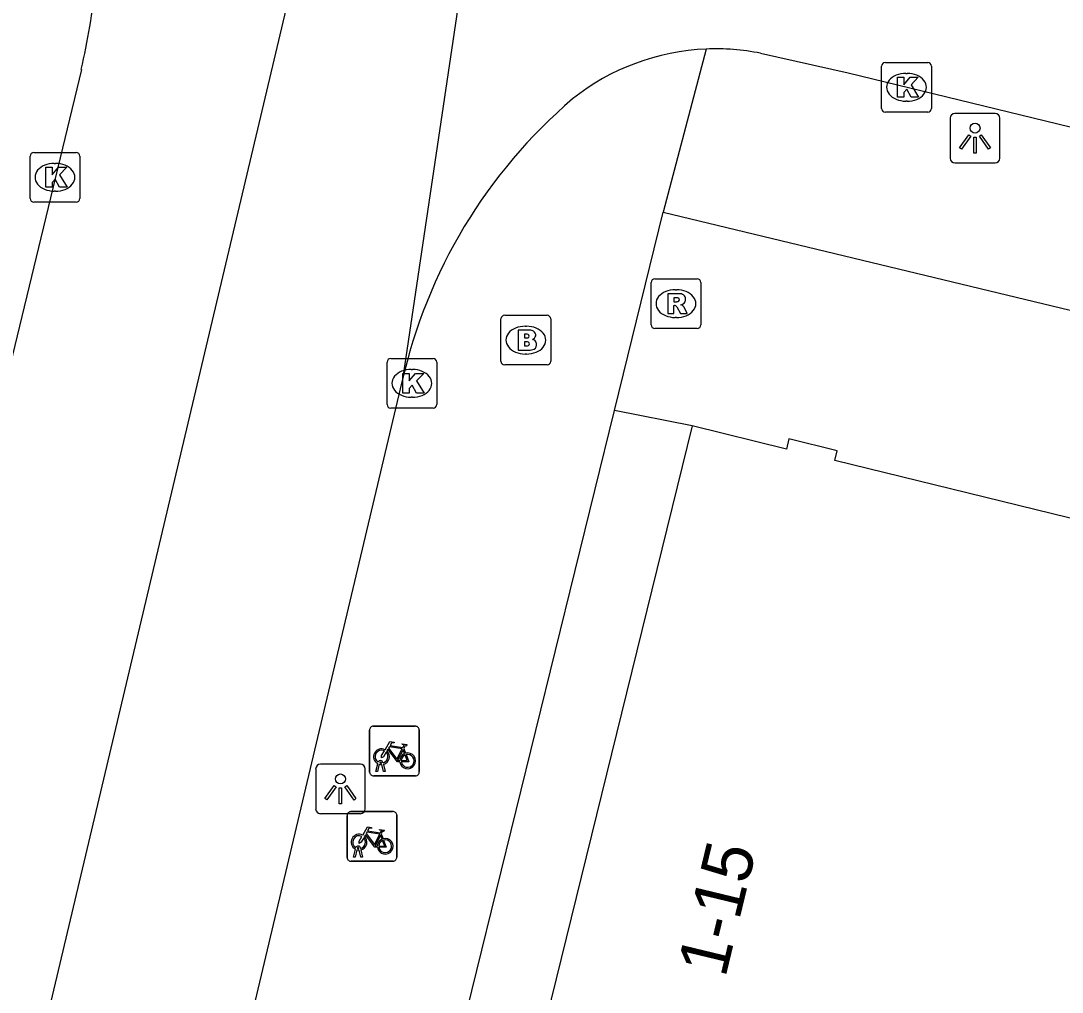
# Model space of a CAD drawing. Extents: x 162812 to 163818, y 381639 to 382470.
# Drawn here: x 163027.55 to 163048.51, y 382341.9 to 382361.46 of the extents above; entities that cross this region are included whole.
import ezdxf

# ---------------------------------------------------------------- set-up
doc = ezdxf.new("R2010")
doc.units = 0
for name, color, linetype in [('IMGEO_Brandkraan', 7, 'Continuous'), ('IMGEO_Fietsenrek', 7, 'Continuous'), ('IMGEO_Kolk', 7, 'Continuous'), ('IMGEO_Lichtpunt', 7, 'Continuous'), ('IMGEO_Pand', 7, 'Continuous'), ('IMGEO_Pand_nummerreeks', 7, 'Continuous'), ('IMGEO_Rijbaan_lokaal_gesloten', 7, 'Continuous'), ('IMGEO_Rijbaan_lokaal_open', 7, 'Continuous'), ('IMGEO_Rioolput', 7, 'Continuous'), ('IMGEO_Voetpad_open', 7, 'Continuous')]:
    doc.layers.add(name, color=color, linetype=linetype)

msp = doc.modelspace()

# ---------------------------------------------------------------- linework, layer by layer
at = {"layer": 'IMGEO_Brandkraan'}
for p, q in [((163037.286, 382355.533), (163038.138, 382355.533)), ((163037.211, 382354.607), (163037.211, 382355.459)), ((163037.699, 382355.313), (163037.724, 382355.313)), ((163038.212, 382355.459), (163038.212, 382354.607)), ((163037.722, 382354.753), (163037.697, 382354.753)), ((163038.138, 382354.533), (163037.286, 382354.533))]:
    msp.add_line(p, q, dxfattribs=at)
for points in [[(163037.286, 382355.533), (163038.138, 382355.533)], [(163037.211, 382354.607), (163037.211, 382355.459)], [(163038.212, 382355.459), (163038.212, 382354.607)], [(163037.559, 382355.233), (163037.559, 382354.833), (163037.772, 382354.833)], [(163037.79, 382355.233), (163037.559, 382355.233)], [(163037.738, 382355.152), (163037.684, 382355.152), (163037.684, 382355.076)], [(163037.684, 382355.076), (163037.737, 382355.076)], [(163037.746, 382355), (163037.684, 382355), (163037.684, 382354.919)], [(163037.684, 382354.919), (163037.746, 382354.919)], [(163038.138, 382354.533), (163037.286, 382354.533)]]:
    msp.add_lwpolyline(points, dxfattribs=at)
for centre, radius, start, end in [((163037.288, 382355.457), 0.0765, 91.552, 178.448), ((163037.288, 382355.457), 0.0765, 91.552, 178.448), ((163038.136, 382355.457), 0.0765, 1.552, 88.448), ((163038.136, 382355.457), 0.0765, 1.552, 88.448), ((163037.739, 382355.114), 0.0379, 267.8285, 90.9355), ((163037.794, 382355.088), 0.145, 59.4692, 91.5367), ((163037.819, 382355.135), 0.0922, 285.5137, 58.1501), ((163037.747, 382354.959), 0.0404, 269.8759, 90.5077), ((163037.778, 382355.084), 0.251, 268.6676, 293.5347), ((163037.824, 382354.943), 0.105, 301.3115, 78.989), ((163037.288, 382354.609), 0.0765, 181.552, 268.448), ((163037.288, 382354.609), 0.0765, 181.552, 268.448), ((163038.136, 382354.609), 0.0765, 271.552, 358.448), ((163038.136, 382354.609), 0.0765, 271.552, 358.448)]:
    msp.add_arc(centre, radius, start, end, dxfattribs=at)
for centre, major_axis, ratio, start_param, end_param in [((163037.698, 382355.033), (-0.387, 0.002), 0.722429, 4.712389, 7.853982), ((163037.723, 382355.033), (-0.39, 0.002), 0.717154, 1.570796, 4.712389)]:
    msp.add_ellipse(centre, major_axis=major_axis, ratio=ratio, start_param=start_param, end_param=end_param, dxfattribs=at)
at = {"layer": 'IMGEO_Fietsenrek'}
for p, q in [((163034.566, 382346.336), (163034.566, 382347.177)), ((163034.566, 382347.177), (163034.566, 382346.336)), ((163034.641, 382347.261), (163035.482, 382347.261)), ((163035.482, 382347.261), (163034.641, 382347.261)), ((163035.566, 382347.186), (163035.566, 382346.345)), ((163035.566, 382346.345), (163035.566, 382347.186)), ((163035.253, 382346.81), (163035.289, 382346.715)), ((163034.693, 382346.345), (163034.732, 382346.505)), ((163034.762, 382346.493), (163034.727, 382346.345)), ((163034.804, 382346.517), (163034.803, 382346.521)), ((163034.845, 382346.345), (163034.811, 382346.487)), ((163034.835, 382346.528), (163034.836, 382346.521)), ((163034.843, 382346.491), (163034.878, 382346.345)), ((163035.491, 382346.261), (163034.65, 382346.261)), ((163034.65, 382346.261), (163035.491, 382346.261)), ((163034.727, 382346.345), (163034.693, 382346.345)), ((163034.878, 382346.345), (163034.845, 382346.345)), ((163034.114, 382344.616), (163034.114, 382345.457)), ((163034.114, 382345.457), (163034.114, 382344.616)), ((163034.189, 382345.541), (163035.03, 382345.541)), ((163035.03, 382345.541), (163034.189, 382345.541)), ((163035.114, 382345.466), (163035.114, 382344.625)), ((163035.114, 382344.625), (163035.114, 382345.466)), ((163034.801, 382345.09), (163034.837, 382344.995)), ((163034.352, 382344.797), (163034.351, 382344.801)), ((163034.383, 382344.808), (163034.384, 382344.801)), ((163034.241, 382344.625), (163034.28, 382344.785)), ((163034.275, 382344.625), (163034.241, 382344.625)), ((163034.31, 382344.773), (163034.275, 382344.625)), ((163034.393, 382344.625), (163034.359, 382344.767)), ((163034.391, 382344.771), (163034.426, 382344.625)), ((163034.426, 382344.625), (163034.393, 382344.625)), ((163035.039, 382344.541), (163034.198, 382344.541)), ((163034.198, 382344.541), (163035.039, 382344.541))]:
    msp.add_line(p, q, dxfattribs=at)
for points in [[(163034.879, 382346.787), (163034.974, 382346.951), (163035.06, 382346.937), (163035.062, 382346.928), (163035.006, 382346.917), (163034.979, 382346.872), (163035.235, 382346.831)], [(163035.235, 382346.831), (163035.26, 382346.88), (163035.254, 382346.884), (163035.231, 382346.888), (163035.219, 382346.895), (163035.218, 382346.898), (163035.22, 382346.903), (163035.315, 382346.888), (163035.317, 382346.878), (163035.307, 382346.865), (163035.295, 382346.859), (163035.281, 382346.865), (163035.253, 382346.81)], [(163034.9, 382346.735), (163034.848, 382346.645), (163034.808, 382346.62), (163034.809, 382346.667), (163034.864, 382346.761)], [(163035.175, 382346.543), (163035.125, 382346.543), (163034.934, 382346.794), (163034.915, 382346.762)], [(163035.222, 382346.806), (163034.965, 382346.847), (163034.948, 382346.818), (163035.115, 382346.598), (163035.222, 382346.806)], [(163035.27, 382346.708), (163035.24, 382346.785), (163035.131, 382346.567), (163035.174, 382346.567)], [(163035.204, 382346.567), (163035.324, 382346.566), (163035.28, 382346.68)], [(163035.3, 382346.687), (163035.355, 382346.542), (163035.205, 382346.542)], [(163034.427, 382345.067), (163034.522, 382345.231), (163034.608, 382345.217), (163034.61, 382345.208), (163034.554, 382345.197), (163034.527, 382345.152), (163034.783, 382345.111)], [(163034.448, 382345.015), (163034.396, 382344.925), (163034.356, 382344.9), (163034.357, 382344.947), (163034.412, 382345.041)], [(163034.723, 382344.823), (163034.673, 382344.823), (163034.482, 382345.074), (163034.463, 382345.042)], [(163034.77, 382345.086), (163034.513, 382345.127), (163034.496, 382345.098), (163034.663, 382344.878), (163034.77, 382345.086)], [(163034.818, 382344.988), (163034.788, 382345.065), (163034.679, 382344.847), (163034.722, 382344.847)], [(163034.783, 382345.111), (163034.808, 382345.16), (163034.802, 382345.164), (163034.779, 382345.168), (163034.767, 382345.175), (163034.766, 382345.178), (163034.768, 382345.183), (163034.863, 382345.168), (163034.865, 382345.158), (163034.855, 382345.145), (163034.843, 382345.139), (163034.829, 382345.145), (163034.801, 382345.09)], [(163034.752, 382344.847), (163034.872, 382344.846), (163034.828, 382344.96)], [(163034.848, 382344.967), (163034.903, 382344.822), (163034.753, 382344.822)]]:
    msp.add_lwpolyline(points, dxfattribs=at)
for centre, radius, start, end in [((163034.644, 382347.183), 0.0779, 92.4484, 184.2845), ((163034.644, 382347.183), 0.0779, 92.4484, 184.2845), ((163035.488, 382347.183), 0.0779, 2.4484, 94.2845), ((163035.488, 382347.183), 0.0779, 2.4484, 94.2845), ((163034.806, 382346.646), 0.159, 62.6766, 242.1369), ((163034.806, 382346.646), 0.129, 63.3192, 238.903), ((163034.806, 382346.646), 0.129, 283.6043, 43.4302), ((163034.806, 382346.646), 0.159, 283.5766, 46.6042), ((163035.333, 382346.562), 0.159, 113.3408, 178.3217), ((163035.333, 382346.562), 0.159, 187.0065, 105.7708), ((163035.333, 382346.562), 0.129, 113.923, 177.9556), ((163035.333, 382346.562), 0.129, 188.6715, 104.5883), ((163034.786, 382346.517), 0.0499, 12.8025, 158.6934), ((163034.806, 382346.646), 0.159, 253.9967, 271.7867), ((163034.786, 382346.517), 0.0174, 12.8025, 163.4502), ((163034.806, 382346.646), 0.129, 253.415, 269.0204), ((163034.644, 382346.339), 0.0779, 182.4484, 274.2845), ((163034.644, 382346.339), 0.0779, 182.4484, 274.2845), ((163035.488, 382346.339), 0.0779, 272.4484, 4.2845), ((163035.488, 382346.339), 0.0779, 272.4484, 4.2845), ((163034.192, 382345.463), 0.0779, 92.4484, 184.2845), ((163034.192, 382345.463), 0.0779, 92.4484, 184.2845), ((163035.036, 382345.463), 0.0779, 2.4484, 94.2845), ((163035.036, 382345.463), 0.0779, 2.4484, 94.2845), ((163034.354, 382344.926), 0.159, 62.6766, 242.1369), ((163034.354, 382344.926), 0.129, 63.3192, 238.903), ((163034.354, 382344.926), 0.129, 283.6043, 43.4302), ((163034.354, 382344.926), 0.159, 283.5766, 46.6042), ((163034.881, 382344.842), 0.159, 187.0065, 105.7708), ((163034.334, 382344.797), 0.0499, 12.8025, 158.6934), ((163034.334, 382344.797), 0.0174, 12.8025, 163.4502), ((163034.354, 382344.926), 0.129, 253.415, 269.0204), ((163034.881, 382344.842), 0.159, 113.3408, 178.3217), ((163034.881, 382344.842), 0.129, 113.923, 177.9556), ((163034.881, 382344.842), 0.129, 188.6715, 104.5883), ((163034.192, 382344.619), 0.0779, 182.4484, 274.2845), ((163034.192, 382344.619), 0.0779, 182.4484, 274.2845), ((163034.354, 382344.926), 0.159, 253.9967, 271.7867), ((163035.036, 382344.619), 0.0779, 272.4484, 4.2845), ((163035.036, 382344.619), 0.0779, 272.4484, 4.2845)]:
    msp.add_arc(centre, radius, start, end, dxfattribs=at)
at = {"layer": 'IMGEO_Kolk'}
for p, q in [((163044.874, 382359.698), (163044.874, 382360.55)), ((163044.949, 382360.624), (163045.801, 382360.624)), ((163045.875, 382360.55), (163045.875, 382359.698)), ((163045.362, 382360.404), (163045.387, 382360.404)), ((163045.385, 382359.844), (163045.36, 382359.844)), ((163045.801, 382359.624), (163044.949, 382359.624)), ((163027.731, 382357.886), (163027.731, 382358.738)), ((163027.806, 382358.812), (163028.658, 382358.812)), ((163028.732, 382358.738), (163028.732, 382357.886)), ((163028.219, 382358.592), (163028.244, 382358.592)), ((163028.242, 382358.032), (163028.217, 382358.032)), ((163028.658, 382357.812), (163027.806, 382357.812)), ((163034.992, 382354.663), (163035.844, 382354.663)), ((163034.917, 382353.737), (163034.917, 382354.589)), ((163035.405, 382354.443), (163035.43, 382354.443)), ((163035.918, 382354.589), (163035.918, 382353.737)), ((163035.428, 382353.883), (163035.403, 382353.883)), ((163035.844, 382353.663), (163034.992, 382353.663))]:
    msp.add_line(p, q, dxfattribs=at)
for points in [[(163044.874, 382359.698), (163044.874, 382360.55)], [(163044.949, 382360.624), (163045.801, 382360.624)], [(163045.875, 382360.55), (163045.875, 382359.698)], [(163045.195, 382360.324), (163045.318, 382360.324), (163045.318, 382360.173), (163045.448, 382360.324), (163045.612, 382360.324), (163045.466, 382360.173), (163045.619, 382359.924), (163045.467, 382359.924), (163045.382, 382360.088), (163045.318, 382360.021), (163045.318, 382359.924), (163045.195, 382359.924), (163045.195, 382360.324)], [(163045.801, 382359.624), (163044.949, 382359.624)], [(163027.731, 382357.886), (163027.731, 382358.738)], [(163027.806, 382358.812), (163028.658, 382358.812)], [(163028.732, 382358.738), (163028.732, 382357.886)], [(163028.052, 382358.512), (163028.175, 382358.512), (163028.175, 382358.361), (163028.305, 382358.512), (163028.469, 382358.512), (163028.323, 382358.361), (163028.476, 382358.112), (163028.324, 382358.112), (163028.239, 382358.276), (163028.175, 382358.209), (163028.175, 382358.112), (163028.052, 382358.112), (163028.052, 382358.512)], [(163028.658, 382357.812), (163027.806, 382357.812)], [(163034.992, 382354.663), (163035.844, 382354.663)], [(163034.917, 382353.737), (163034.917, 382354.589)], [(163035.918, 382354.589), (163035.918, 382353.737)], [(163035.238, 382354.363), (163035.361, 382354.363), (163035.361, 382354.212), (163035.491, 382354.363), (163035.655, 382354.363), (163035.509, 382354.212), (163035.662, 382353.963), (163035.51, 382353.963), (163035.425, 382354.127), (163035.361, 382354.06), (163035.361, 382353.963), (163035.238, 382353.963), (163035.238, 382354.363)], [(163035.844, 382353.663), (163034.992, 382353.663)]]:
    msp.add_lwpolyline(points, dxfattribs=at)
for centre, start, end in [((163044.951, 382360.548), 91.552, 178.448), ((163044.951, 382360.548), 91.552, 178.448), ((163045.799, 382360.548), 1.552, 88.448), ((163045.799, 382360.548), 1.552, 88.448), ((163044.951, 382359.7), 181.552, 268.448), ((163044.951, 382359.7), 181.552, 268.448), ((163045.799, 382359.7), 271.552, 358.448), ((163045.799, 382359.7), 271.552, 358.448), ((163027.808, 382358.736), 91.552, 178.448), ((163027.808, 382358.736), 91.552, 178.448), ((163028.656, 382358.736), 1.552, 88.448), ((163028.656, 382358.736), 1.552, 88.448), ((163027.808, 382357.888), 181.552, 268.448), ((163027.808, 382357.888), 181.552, 268.448), ((163028.656, 382357.888), 271.552, 358.448), ((163028.656, 382357.888), 271.552, 358.448), ((163034.994, 382354.587), 91.552, 178.448), ((163034.994, 382354.587), 91.552, 178.448), ((163035.842, 382354.587), 1.552, 88.448), ((163035.842, 382354.587), 1.552, 88.448), ((163034.994, 382353.739), 181.552, 268.448), ((163034.994, 382353.739), 181.552, 268.448), ((163035.842, 382353.739), 271.552, 358.448), ((163035.842, 382353.739), 271.552, 358.448)]:
    msp.add_arc(centre, 0.0765, start, end, dxfattribs=at)
for centre, major_axis, ratio, start_param, end_param in [((163045.361, 382360.124), (-0.387, 0.002), 0.722429, 4.712389, 7.853982), ((163045.386, 382360.124), (-0.39, 0.002), 0.717154, 1.570796, 4.712389), ((163028.218, 382358.312), (-0.387, 0.002), 0.722429, 4.712389, 7.853982), ((163028.243, 382358.312), (-0.39, 0.002), 0.717154, 1.570796, 4.712389), ((163035.404, 382354.163), (-0.387, 0.002), 0.722429, 4.712389, 7.853982), ((163035.429, 382354.163), (-0.39, 0.002), 0.717154, 1.570796, 4.712389)]:
    msp.add_ellipse(centre, major_axis=major_axis, ratio=ratio, start_param=start_param, end_param=end_param, dxfattribs=at)
at = {"layer": 'IMGEO_Lichtpunt'}
for p, q in [((163046.256, 382359.503), (163046.256, 382358.696)), ((163046.256, 382359.503), (163046.256, 382358.696)), ((163047.158, 382359.598), (163046.35, 382359.598)), ((163047.158, 382359.598), (163046.35, 382359.598)), ((163047.252, 382358.696), (163047.252, 382359.503)), ((163047.252, 382358.696), (163047.252, 382359.503)), ((163046.35, 382358.602), (163047.158, 382358.602)), ((163046.35, 382358.602), (163047.158, 382358.602)), ((163034.383, 382346.495), (163033.575, 382346.495)), ((163034.383, 382346.495), (163033.575, 382346.495)), ((163033.481, 382346.4), (163033.481, 382345.593)), ((163033.481, 382346.4), (163033.481, 382345.593)), ((163034.477, 382345.593), (163034.477, 382346.4)), ((163034.477, 382345.593), (163034.477, 382346.4)), ((163033.575, 382345.499), (163034.383, 382345.499)), ((163033.575, 382345.499), (163034.383, 382345.499))]:
    msp.add_line(p, q, dxfattribs=at)
for points in [[(163046.63, 382359.167), (163046.669, 382359.139), (163046.481, 382358.877), (163046.443, 382358.904), (163046.63, 382359.167)], [(163046.732, 382359.119), (163046.779, 382359.119), (163046.779, 382358.797), (163046.732, 382358.797), (163046.732, 382359.119)], [(163046.842, 382359.139), (163046.88, 382359.166), (163047.067, 382358.904), (163047.028, 382358.876), (163046.842, 382359.139)], [(163033.855, 382346.064), (163033.894, 382346.036), (163033.706, 382345.774), (163033.668, 382345.801), (163033.855, 382346.064)], [(163034.067, 382346.036), (163034.105, 382346.063), (163034.292, 382345.801), (163034.253, 382345.773), (163034.067, 382346.036)], [(163033.957, 382346.016), (163034.004, 382346.016), (163034.004, 382345.694), (163033.957, 382345.694), (163033.957, 382346.016)]]:
    msp.add_lwpolyline(points, dxfattribs=at)
for centre in [(163046.755, 382359.301), (163033.98, 382346.198)]:
    msp.add_circle(centre, 0.0994, dxfattribs=at)
for centre, start, end in [((163046.35, 382359.503), 90, 180), ((163046.35, 382359.503), 90, 180), ((163047.158, 382359.503), 0, 90), ((163047.158, 382359.503), 0, 90), ((163046.35, 382358.696), 180, 270), ((163046.35, 382358.696), 180, 270), ((163047.158, 382358.696), 270, 0), ((163047.158, 382358.696), 270, 360), ((163033.575, 382346.4), 90, 180), ((163033.575, 382346.4), 90, 180), ((163034.383, 382346.4), 0, 90), ((163034.383, 382346.4), 0, 90), ((163033.575, 382345.593), 180, 270), ((163033.575, 382345.593), 180, 270), ((163034.383, 382345.593), 270, 0), ((163034.383, 382345.593), 270, 360)]:
    msp.add_arc(centre, 0.0946, start, end, dxfattribs=at)
at = {"layer": 'IMGEO_Pand'}
for points in [[(163041.059, 382353.306), (163036.903, 382336.391)], [(163050.133, 382350.305), (163050.315, 382351.044), (163043.932, 382352.612), (163043.98, 382352.805), (163043.006, 382353.044), (163042.956, 382352.84), (163041.059, 382353.306)]]:
    msp.add_lwpolyline(points, dxfattribs=at)
at = {"layer": 'IMGEO_Rijbaan_lokaal_gesloten'}
for points in [[(163020.941, 382328.112), (163024.715, 382327.217), (163035.23, 382371.584)], [(163035.23, 382371.584), (163036.585, 382363.359), (163035.219, 382354.192)], [(163042.433, 382360.809), (163044.202, 382360.414), (163096.339, 382347.729), (163098.264, 382347.275)], [(163027.611, 382322.091), (163035.219, 382354.192)]]:
    msp.add_lwpolyline(points, dxfattribs=at)
for centre, radius, start, end in [((163041.531, 382356.281), 4.616, 92.337, 128.6071), ((163041.542, 382356.361), 4.536, 78.6719, 92.5147), ((163045.489, 382351.886), 10.526, 130.5153, 167.3444)]:
    msp.add_arc(centre, radius, start, end, dxfattribs=at)
at = {"layer": 'IMGEO_Rijbaan_lokaal_open'}
msp.add_lwpolyline([(163028.764, 382360.48), (163020.941, 382328.112)], dxfattribs=at)
msp.add_arc((163007.848, 382365.047), 21.408, 347.6824, 352.4252, dxfattribs=at)
at = {"layer": 'IMGEO_Rioolput'}
for p, q in [((163040.232, 382355.342), (163040.232, 382356.194)), ((163040.307, 382356.268), (163041.159, 382356.268)), ((163041.233, 382356.194), (163041.233, 382355.342)), ((163040.72, 382356.048), (163040.745, 382356.048)), ((163040.743, 382355.488), (163040.718, 382355.488)), ((163041.159, 382355.268), (163040.307, 382355.268))]:
    msp.add_line(p, q, dxfattribs=at)
for points in [[(163040.232, 382355.342), (163040.232, 382356.194)], [(163040.307, 382356.268), (163041.159, 382356.268)], [(163041.233, 382356.194), (163041.233, 382355.342)], [(163040.821, 382355.966), (163040.569, 382355.968), (163040.569, 382355.568)], [(163040.569, 382355.568), (163040.693, 382355.568), (163040.693, 382355.73), (163040.704, 382355.73)], [(163040.747, 382355.887), (163040.693, 382355.887), (163040.693, 382355.806)], [(163040.693, 382355.806), (163040.745, 382355.806)], [(163040.751, 382355.701), (163040.822, 382355.568), (163040.962, 382355.568), (163040.897, 382355.694)], [(163041.159, 382355.268), (163040.307, 382355.268)]]:
    msp.add_lwpolyline(points, dxfattribs=at)
for centre, radius, start, end in [((163040.309, 382356.192), 0.0765, 91.552, 178.448), ((163040.309, 382356.192), 0.0765, 91.552, 178.448), ((163041.157, 382356.192), 0.0765, 1.552, 88.448), ((163041.157, 382356.192), 0.0765, 1.552, 88.448), ((163040.82, 382355.856), 0.109, 350.3612, 89.416), ((163040.703, 382355.677), 0.0533, 26.0293, 88.6989), ((163040.729, 382355.995), 0.19, 274.7715, 282.9687), ((163040.753, 382355.791), 0.0964, 77.0061, 93.1865), ((163040.767, 382355.848), 0.0378, 276.6634, 79.6772), ((163040.818, 382355.856), 0.112, 277.5842, 350.9817), ((163040.802, 382355.641), 0.108, 29.5134, 73.7905), ((163040.309, 382355.344), 0.0765, 181.552, 268.448), ((163040.309, 382355.344), 0.0765, 181.552, 268.448), ((163041.157, 382355.344), 0.0765, 271.552, 358.448), ((163041.157, 382355.344), 0.0765, 271.552, 358.448)]:
    msp.add_arc(centre, radius, start, end, dxfattribs=at)
for centre, major_axis, ratio, start_param, end_param in [((163040.719, 382355.768), (-0.387, 0.002), 0.722429, 4.712389, 7.853982), ((163040.744, 382355.768), (-0.39, 0.002), 0.717154, 1.570796, 4.712389)]:
    msp.add_ellipse(centre, major_axis=major_axis, ratio=ratio, start_param=start_param, end_param=end_param, dxfattribs=at)
at = {"layer": 'IMGEO_Voetpad_open'}
for points in [[(163041.343, 382360.893), (163040.477, 382357.61)], [(163039.496, 382353.616), (163040.477, 382357.61)], [(163040.477, 382357.61), (163097.296, 382343.924)], [(163032.719, 382319.365), (163031.184, 382319.792), (163039.496, 382353.616)], [(163041.059, 382353.306), (163039.496, 382353.616)]]:
    msp.add_lwpolyline(points, dxfattribs=at)

# ---------------------------------------------------------------- texts
at = {"layer": 'IMGEO_Pand_nummerreeks'}
msp.add_text('1-15', height=1, rotation=76.4538, dxfattribs=at).set_placement((163041.726, 382342.175))

doc.saveas('drawing.dxf')
